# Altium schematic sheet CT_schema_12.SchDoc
size 389 x 385 mm
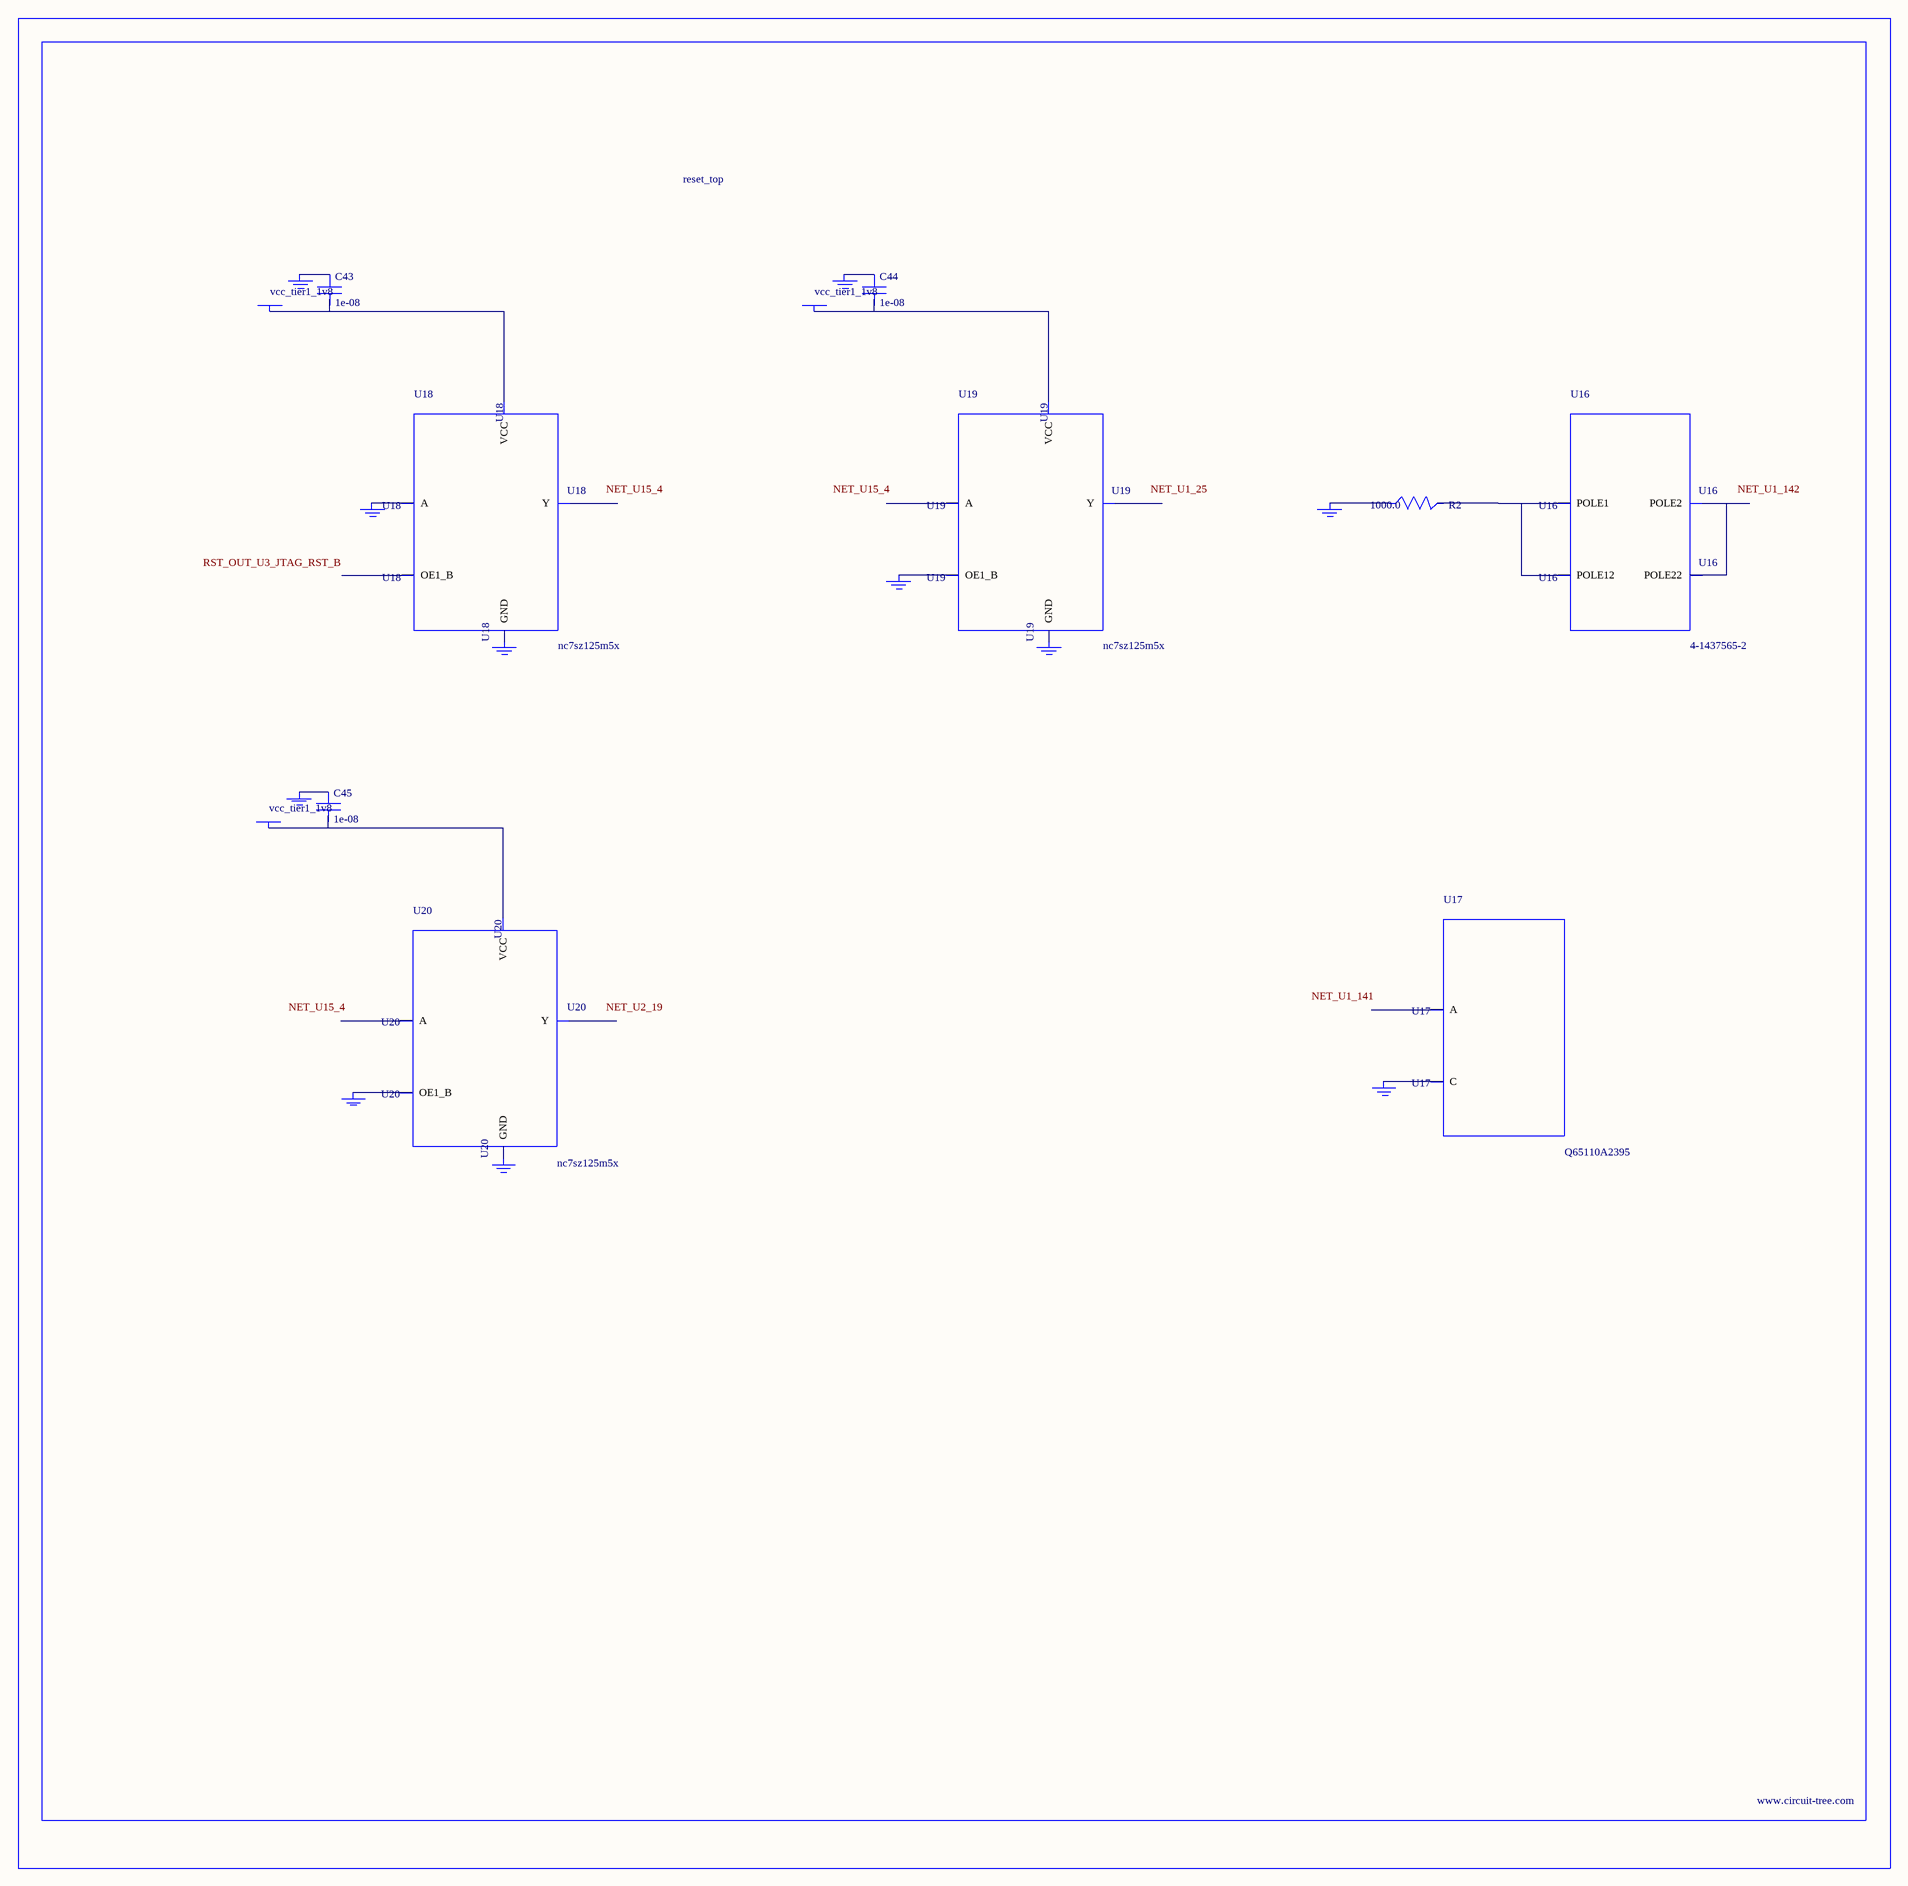
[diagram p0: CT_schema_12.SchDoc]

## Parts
BORDER11  (no value)
C43  1e-08  [C0402]
C44  1e-08  [C0402]
C45  1e-08  [C0402]
GND_INSTANCE_11_0  (no value)
GND_INSTANCE_11_1  (no value)
GND_INSTANCE_11_2  (no value)
GND_INSTANCE_11_3  (no value)
GND_INSTANCE_11_4  (no value)
GND_INSTANCE_11_5  (no value)
GND_INSTANCE_11_6  (no value)
GND_INSTANCE_11_7  (no value)
GND_INSTANCE_11_8  (no value)
GND_INSTANCE_11_9  (no value)
GND_INSTANCE_11_10  (no value)
POWER_INSTANCE_11_0  vcc_tier1_1v8
POWER_INSTANCE_11_1  vcc_tier1_1v8
POWER_INSTANCE_11_2  vcc_tier1_1v8
R2  1000.0  [R0603]
U16  4-1437565-2  [SW_4-1437565-2]
U17  Q65110A2395  [LGM67K-G1J2-24-Z]
U18  nc7sz125m5x  [NC7SZ125M5X]
U19  nc7sz125m5x  [NC7SZ125M5X]
U20  nc7sz125m5x  [NC7SZ125M5X]

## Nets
NetC43_1: C43.1 GND_INSTANCE_11_2.0(GND)
NetC43_2: C43.2 POWER_INSTANCE_11_0.0(PWR) U18.5(VCC)
NetC44_1: C44.1 GND_INSTANCE_11_5.0(GND)
NetC44_2: C44.2 POWER_INSTANCE_11_1.0(PWR) U19.5(VCC)
NetC45_1: C45.1 GND_INSTANCE_11_8.0(GND)
NetC45_2: C45.2 POWER_INSTANCE_11_2.0(PWR) U20.5(VCC)
NetGND_INSTANCE_11_0_0: GND_INSTANCE_11_0.0(GND) R2.1
NetGND_INSTANCE_11_1_0: GND_INSTANCE_11_1.0(GND) U17.C
NetGND_INSTANCE_11_3_0: GND_INSTANCE_11_3.0(GND) U18.2(A)
NetGND_INSTANCE_11_4_0: GND_INSTANCE_11_4.0(GND) U18.3(GND)
NetGND_INSTANCE_11_6_0: GND_INSTANCE_11_6.0(GND) U19.1(OE1_B)
NetGND_INSTANCE_11_7_0: GND_INSTANCE_11_7.0(GND) U19.3(GND)
NetGND_INSTANCE_11_9_0: GND_INSTANCE_11_9.0(GND) U20.1(OE1_B)
NetGND_INSTANCE_11_10_0: GND_INSTANCE_11_10.0(GND) U20.3(GND)
NetR2_2: R2.2 U16.1(POLE1) U16.2(POLE12)
NetU16_3: U16.3(POLE2) U16.4(POLE22)

Not connected (* = marked no-connect by the designer): U17 A; U18 1(OE1_B) 4(Y); U19 2(A) 4(Y); U20 2(A) 4(Y)

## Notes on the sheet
- Labels drawn without touching a wire or pin: NET_U1_25, NET_U1_141, NET_U1_142, NET_U2_19, NET_U15_4, RST_OUT_U3_JTAG_RST_B

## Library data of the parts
BORDER11 = BORDER_PAGE11
C43-C45 = C0402C103K3RAC
GND_INSTANCE_11_0-GND_INSTANCE_11_10 = GND
POWER_INSTANCE_11_0-POWER_INSTANCE_11_2 = PWR
R2 = RC0603JR-071KL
